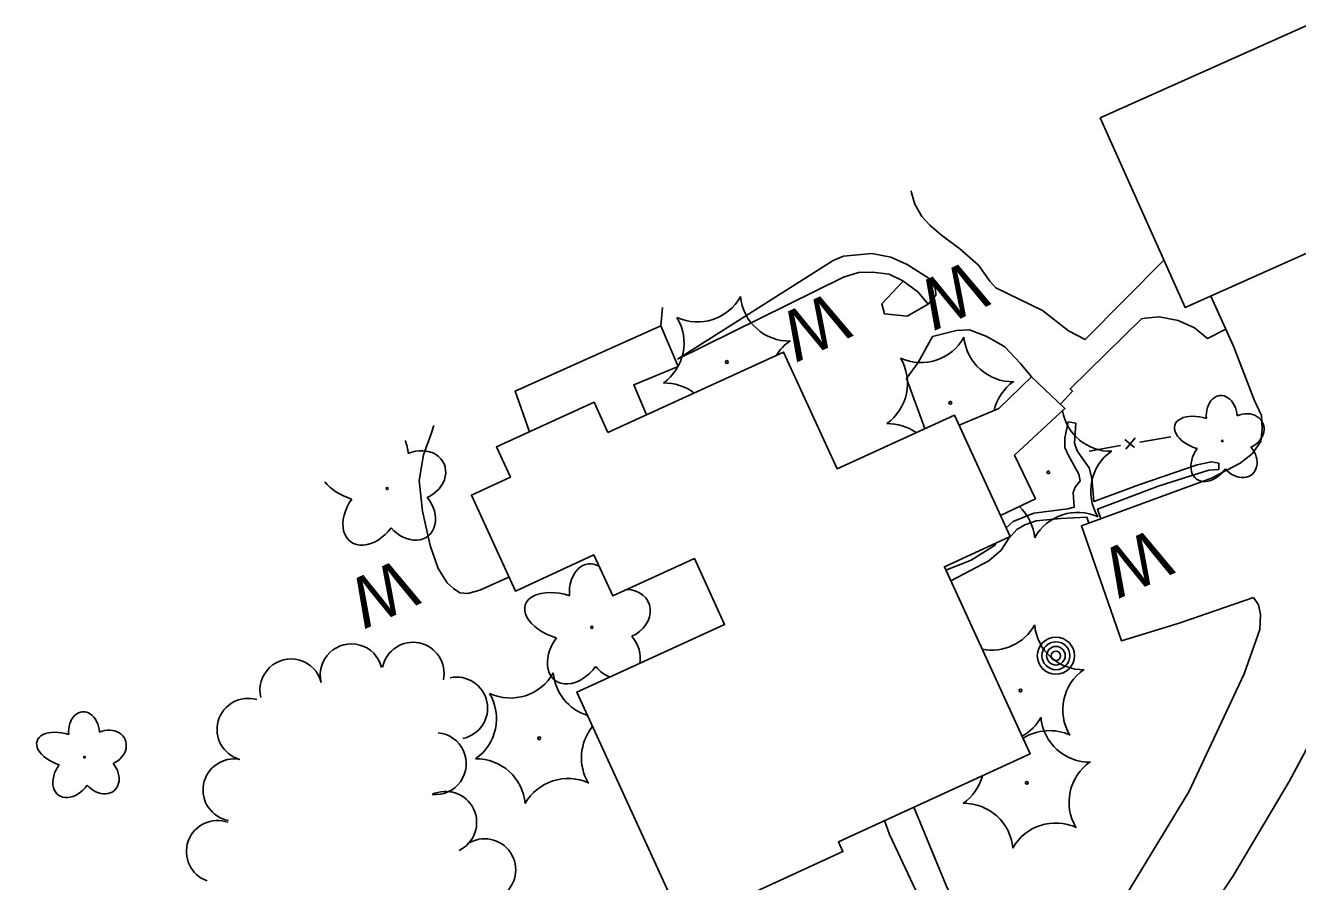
# Model space of a CAD drawing. Extents: x 588843 to 2552415, y 180129 to 269402.
# Drawn here: x 593432.8 to 593585.5, y 188219.4 to 188322.2 of the extents above; entities that cross this region are included whole.
import ezdxf

# ---------------------------------------------------------------- set-up
doc = ezdxf.new("R2010")
doc.units = 0
for name, color, linetype in [('Default', 7, 'Continuous'), ('E_BLD', 7, 'Continuous'), ('E_BLD_HvyDash', 7, 'Continuous'), ('E_DWY', 7, 'Continuous'), ('E_FEN_P', 7, 'Continuous'), ('E_LAND_TreeLine_P', 7, 'Continuous'), ('E_LAND_Vegetation', 7, 'Continuous'), ('E_MISCPROP', 7, 'Continuous'), ('E_MISCPROP_ShtDash', 7, 'Continuous'), ('E_PATH_Sidewalk', 7, 'Continuous'), ('E_WAL', 7, 'Continuous'), ('E_WAL_Text', 7, 'Continuous')]:
    doc.layers.add(name, color=color, linetype=linetype)

# ---------------------------------------------------------------- blocks, each defined once
blk = doc.blocks.new('W_24')
at = {"layer": 'E_WAL_Text'}
blk.add_text('W', height=12, dxfattribs=at).set_placement((-4.46, -6))
blk = doc.blocks.new('POLE')
at = {"layer": 'Default'}
for radius in [4.46, 3.35, 2.23, 1.12]:
    blk.add_circle((0, 0), radius, dxfattribs=at)
blk = doc.blocks.new('W_25')
at = {"layer": 'E_WAL_Text'}
blk.add_text('W', height=12, dxfattribs=at).set_placement((-4.46, -6))
blk = doc.blocks.new('DTRE')
at = {"layer": 'Default'}
blk.add_circle((-0.18, 0), 0.183, dxfattribs=at)
for centre, major_axis, ratio in [((-1.87, 5.32), (1.36, -4.98), 0.782863), ((4.06, 2.74), (-5.27, -2.93), 0.691916), ((-5.87, 0.15), (4.93, -0.12), 0.832022), ((3.54, -3.71), (-5.01, 4.58), 0.560249), ((-2.49, -5.24), (1.8, 4.86), 0.716896)]:
    blk.add_ellipse(centre, major_axis=major_axis, ratio=ratio, start_param=1.570796, end_param=4.712389, dxfattribs=at)
blk = doc.blocks.new('U299')
at = {"layer": 'E_LAND_Vegetation'}
blk.add_circle((0, -0.02), 0.167, dxfattribs=at)
for centre, radius, start, end in [((-3.53, 10.69), 5.9, 245.3645, 331.1294), ((7.51, 8.39), 5.9, 185.3644, 271.1294), ((-11.05, 2.28), 5.91, 305.4042, 31.0803), ((10.99, -2.29), 5.9, 125.3598, 148.5907), ((-7.51, -8.43), 5.9, 52.6355, 91.1294)]:
    blk.add_arc(centre, radius, start, end, dxfattribs=at)
blk = doc.blocks.new('U300')
at = {"layer": 'E_LAND_Vegetation'}
blk.add_circle((0, -0.02), 0.167, dxfattribs=at)
for centre, radius, start, end in [((-3.46, 10.71), 5.9, 299.2891, 330.7612), ((7.57, 8.35), 5.9, 184.9962, 270.7611), ((10.97, -2.36), 5.9, 124.9916, 210.7565), ((-11.03, 2.35), 5.91, 305.036, 345.0302), ((-7.56, -8.38), 5.9, 4.9962, 90.7612), ((3.46, -10.75), 5.9, 64.9962, 150.7611)]:
    blk.add_arc(centre, radius, start, end, dxfattribs=at)
blk = doc.blocks.new('U302')
at = {"layer": 'E_LAND_Vegetation'}
blk.add_circle((0.09, 0.03), 0.128, dxfattribs=at)
for centre, major_axis, ratio, start_param, end_param in [((0.01, 4.04), (0.28, -3.62), 0.716896, 2.648424, 4.712389), ((-3.37, 1.29), (4.53, -1.44), 0.560249, 1.570796, 4.712389), ((3.75, 1.6), (-3.17, -1.37), 0.832022, 1.570796, 4.204524), ((-1.81, -2.95), (2.49, 3.41), 0.691916, 1.570796, 4.712389), ((2.72, -2.86), (-2.33, 2.77), 0.782863, 3.681681, 4.712389), ((2.72, -2.86), (-2.33, 2.77), 0.782863, 1.570796, 2.176121)]:
    blk.add_ellipse(centre, major_axis=major_axis, ratio=ratio, start_param=start_param, end_param=end_param, dxfattribs=at)
blk = doc.blocks.new('U303')
at = {"layer": 'E_LAND_Vegetation'}
blk.add_circle((0, -0.02), 0.167, dxfattribs=at)
for centre, radius, start, end in [((-3.46, 10.71), 5.9, 244.9962, 330.7612), ((7.57, 8.35), 5.9, 184.9962, 252.7866), ((-11.03, 2.35), 5.91, 305.036, 30.7121), ((10.97, -2.36), 5.9, 140.4864, 210.7565), ((-7.56, -8.38), 5.9, 4.9962, 90.7612), ((3.46, -10.75), 5.9, 64.9962, 150.7611)]:
    blk.add_arc(centre, radius, start, end, dxfattribs=at)
blk = doc.blocks.new('U304')
at = {"layer": 'E_LAND_Vegetation'}
blk.add_circle((0, -0.02), 0.167, dxfattribs=at)
for centre, start, end in [((-3.46, 10.71), 258.7145, 330.7612), ((7.57, 8.35), 184.9962, 270.7611), ((10.97, -2.36), 124.9916, 210.7565), ((3.46, -10.75), 64.9962, 122.5325)]:
    blk.add_arc(centre, 5.9, start, end, dxfattribs=at)

msp = doc.modelspace()

# ---------------------------------------------------------------- linework, layer by layer
at = {"layer": 'E_BLD'}
for points in [[(593561.83, 188311.1), (593586.61, 188322.2), (593596.81, 188299.42), (593572.04, 188288.32), (593561.83, 188311.1)], [(593502.75, 188273.33), (593523.82, 188282.99), (593530.24, 188268.98), (593544.33, 188275.43), (593551.02, 188260.84), (593543.12, 188257.21), (593553.42, 188234.75), (593530.4, 188224.2), (593530.95, 188223.01), (593511.83, 188214.24), (593499.02, 188242.17), (593516.74, 188250.3), (593513.12, 188258.2), (593503.32, 188253.71), (593501.07, 188258.63), (593491.63, 188254.3), (593486.36, 188265.8), (593491.04, 188267.95), (593489.37, 188271.6), (593501.08, 188276.97), (593502.75, 188273.33)]]:
    msp.add_lwpolyline(points, close=True, dxfattribs=at)
at = {"layer": 'E_BLD_HvyDash'}
for points in [[(593493.32, 188273.41), (593491.59, 188278.28), (593509.09, 188286.14), (593511.16, 188281.26), (593505.84, 188279.04), (593507.39, 188275.46)], [(593544.89, 188274.21), (593549.67, 188276.22), (593553.59, 188280.01), (593557.6, 188276.23), (593551.56, 188270.62), (593554.06, 188265.37), (593549.86, 188263.36)]]:
    msp.add_lwpolyline(points, dxfattribs=at)
at = {"layer": 'E_DWY'}
for points in [[(593575.12, 188289.7), (593577.83, 188283.68), (593580.29, 188277.25), (593581.18, 188275.39), (593581.25, 188273.74), (593581.1, 188272.24), (593580.07, 188270.77), (593578.61, 188269.66), (593575.17, 188267.86)], [(593539.8, 188134.18), (593535.15, 188137.59), (593532.54, 188139.85), (593531.46, 188141.45), (593530.53, 188143.73), (593530.3, 188146.14), (593530.39, 188149.61), (593531.59, 188155.73), (593533.85, 188163.21), (593535.47, 188166.5), (593537.46, 188169.6), (593562.1, 188198.46), (593569.6, 188207.86), (593577.78, 188220.1), (593584.5, 188231.42), (593594.27, 188249.63), (593596.74, 188253.25), (593607.35, 188261.74), (593615.26, 188265.86), (593629.22, 188272.13)], [(593580.22, 188253.53), (593580.84, 188252.63), (593581.07, 188251.47), (593580.97, 188249.67), (593579.12, 188244.35), (593572.45, 188230.21), (593562.98, 188214.6)]]:
    msp.add_lwpolyline(points, dxfattribs=at)
at = {"layer": 'E_FEN_P'}
for p, q in [((593564.78, 188272.48), (593565.96, 188271.54)), ((593564.92, 188271.33), (593566.03, 188272.7))]:
    msp.add_line(p, q, dxfattribs=at)
for points in [[(593566.57, 188272.17), (593570.32, 188272.82)], [(593560.5, 188271.1), (593564.25, 188271.76)]]:
    msp.add_lwpolyline(points, dxfattribs=at)
at = {"layer": 'E_LAND_TreeLine_P'}
for centre, start, end in [((593471.95, 188244.23), 13.9987, 193.9987), ((593479.35, 188244.41), 348.1736, 168.1736), ((593464.71, 188242.42), 13.9987, 193.9987), ((593484.57, 188240.24), 281.8643, 101.8643), ((593459.56, 188237.68), 74.0614, 254.0614), ((593482, 188233.58), 264.325, 84.325), ((593457.88, 188230.42), 79.5329, 259.5329), ((593483.26, 188226.51), 295.8966, 115.8966), ((593455.88, 188223.02), 70.3181, 250.3181), ((593487.94, 188220.83), 298.1541, 118.1541)]:
    msp.add_arc(centre, 3.73, start, end, dxfattribs=at)
at = {"layer": 'E_LAND_Vegetation'}
for centre, radius in [((593543.84, 188276.91), 0.167), ((593555.6, 188268.55), 0.167), ((593476.25, 188266.61), 0.128)]:
    msp.add_circle(centre, radius, dxfattribs=at)
for centre, radius, start, end in [((593540.31, 188287.62), 5.9, 245.3645, 331.1294), ((593551.35, 188285.32), 5.9, 185.3644, 271.1294), ((593532.79, 188279.21), 5.91, 305.4042, 31.0803), ((593554.83, 188274.64), 5.9, 125.3598, 167.0301), ((593563.11, 188276.97), 5.9, 189.9748, 271.1294), ((593536.33, 188268.5), 5.9, 54.849, 91.1294), ((593566.59, 188266.29), 5.9, 125.3598, 211.1247), ((593548.09, 188260.14), 5.9, 5.3645, 46.8189), ((593559.13, 188257.85), 5.9, 65.3644, 151.1294)]:
    msp.add_arc(centre, radius, start, end, dxfattribs=at)
for centre, major_axis, ratio, start_param, end_param in [((593476.18, 188270.62), (0.28, -3.62), 0.716896, 1.570796, 2.02146), ((593479.91, 188268.18), (-3.17, -1.37), 0.832022, 1.570796, 4.712389), ((593472.79, 188267.87), (4.53, -1.44), 0.560249, 3.818022, 4.712389), ((593474.36, 188263.62), (2.49, 3.41), 0.691916, 1.570796, 4.712389), ((593478.88, 188263.72), (-2.33, 2.77), 0.782863, 1.570796, 4.712389)]:
    msp.add_ellipse(centre, major_axis=major_axis, ratio=ratio, start_param=start_param, end_param=end_param, dxfattribs=at)
at = {"layer": 'E_MISCPROP_ShtDash'}
msp.add_lwpolyline([(593580.22, 188253.53), (593571.3, 188250.44)], dxfattribs=at)
at = {"layer": 'E_PATH_Sidewalk'}
for points in [[(593569.47, 188294.04), (593560.02, 188284.49), (593558.01, 188285.52), (593556.19, 188286.98), (593554.91, 188287.98), (593549.3, 188290.71), (593548.57, 188291.48), (593547.22, 188293.41), (593544.97, 188295.4), (593542.76, 188297.01), (593541.38, 188298.22), (593540.4, 188299.27), (593539.57, 188300.73), (593539.17, 188302.1), (593539.15, 188302.35)], [(593541.16, 188288.74), (593542.11, 188289.82), (593542.06, 188290.56), (593541.29, 188291.81), (593538.64, 188293.5), (593536.68, 188294.39), (593534.41, 188294.84), (593531.03, 188294.49), (593529.79, 188293.97), (593511.1, 188282.13)], [(593541.16, 188288.74), (593538.65, 188287.31), (593535.94, 188287.59), (593535.61, 188288.78), (593538.18, 188291.51)], [(593576.91, 188285.72), (593574.69, 188284.62), (593573.16, 188285.89), (593571.2, 188286.79), (593568.91, 188287.22), (593567.21, 188287.07), (593566.8, 188286.96), (593558.22, 188278.59), (593558.51, 188278.28), (593557.05, 188276.74)], [(593541.7, 188284.85), (593539.98, 188281.73), (593538.59, 188279.8), (593540.78, 188273.8)], [(593550.54, 188261.87), (593551.4, 188262.63), (593553.85, 188263.65), (593557.95, 188264.16), (593558.72, 188264.35), (593558.6, 188266.12), (593558.83, 188266.78), (593559.43, 188267.51), (593559.25, 188268.34), (593558.04, 188270.56), (593557.58, 188271.55), (593557.57, 188272.67), (593557.97, 188274.61), (593558.92, 188274.44), (593558.76, 188272.06), (593559.08, 188271.15), (593559.89, 188269.94), (593560.51, 188269.09), (593560.83, 188267.83), (593561.08, 188265.04), (593566.6, 188267.07), (593573.46, 188269.44), (593575.19, 188269.81), (593576.06, 188269.66), (593576.05, 188268.89), (593574.88, 188268.8), (593568.89, 188266.91), (593561.51, 188264.13), (593561.9, 188262.97)], [(593560.45, 188262.44), (593560.21, 188263.18), (593557.12, 188263.02), (593554.14, 188262.72), (593552.79, 188262.24), (593551.83, 188261.7), (593550.83, 188260.58), (593549.95, 188259.22), (593548.48, 188257.92), (593543.89, 188255.54)], [(593543.31, 188256.8), (593546.33, 188258), (593549.13, 188259.78), (593549.29, 188260.04)], [(593552.91, 188201.83), (593552.06, 188201.84), (593551.46, 188202.03), (593550.98, 188202.86), (593543.32, 188218.96), (593539.45, 188228.35)], [(593548.95, 188197.3), (593548.93, 188198.34), (593548.53, 188199.54), (593536.54, 188225.07), (593535.94, 188226.74)]]:
    msp.add_lwpolyline(points, dxfattribs=at)
at = {"layer": 'E_WAL'}
for points in [[(593541.16, 188288.74), (593539.95, 188290.2), (593538.15, 188291.53), (593536.49, 188292.34), (593534.52, 188292.58), (593532.8, 188292.54), (593531.02, 188291.98), (593511.1, 188282.13)], [(593509.31, 188288.32), (593509.09, 188286.14)], [(593553.59, 188280.01), (593552.21, 188281.67), (593550.39, 188283.6), (593548.24, 188284.85), (593546.12, 188285.66), (593544.58, 188285.56), (593541.7, 188284.85)], [(593481.86, 188274.16), (593481.51, 188273.19), (593480.62, 188270.65), (593480.09, 188267.55), (593480.47, 188263.87), (593481.42, 188259.75), (593482.36, 188257.01), (593483.43, 188255.29), (593484.2, 188254.6), (593484.98, 188254.07), (593485.94, 188254.01), (593487.36, 188254.42), (593490.86, 188255.97)], [(593571.3, 188250.44), (593564.38, 188248.32), (593559.58, 188262.12), (593575.17, 188267.86)]]:
    msp.add_lwpolyline(points, dxfattribs=at)

# ---------------------------------------------------------------- block references
at = {"layer": 'E_LAND_Vegetation'}
for name, p in [('U299', (593517.02, 188281.81)), ('U302', (593500.72, 188249.91)), ('U304', (593552.27, 188242.39)), ('U303', (593494.49, 188236.64)), ('U300', (593553.02, 188231.3))]:
    msp.add_blockref(name, p, dxfattribs=at)
for p, xscale, yscale, rotation in [((593576.41, 188272.28), 0.49999999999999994, 0.49999999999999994, -154.84687668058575), ((593439.84, 188234.32), 0.5, 0.5, -155.21508863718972)]:
    msp.add_blockref('DTRE', p, dxfattribs=dict(at, xscale=xscale, yscale=yscale, rotation=rotation))
at = {"layer": 'E_MISCPROP', "xscale": 0.5, "yscale": 0.5, "rotation": -155.21508863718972}
msp.add_blockref('POLE', (593556.51, 188246.53), dxfattribs=at)
at = {"layer": 'E_WAL_Text'}
for name, p, xscale, yscale, rotation in [('W_25', (593545.53, 188290.53), 0.49999999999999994, 0.49999999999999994, -154.84687668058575), ('W_25', (593528.98, 188286.73), 0.49999999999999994, 0.49999999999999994, -154.84687668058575), ('W_24', (593567.67, 188258.33), 0.5, 0.5, -155.21508863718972), ('W_24', (593477.18, 188254.69), 0.5, 0.5, -155.21508863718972)]:
    msp.add_blockref(name, p, dxfattribs=dict(at, xscale=xscale, yscale=yscale, rotation=rotation))

doc.saveas('drawing.dxf')
